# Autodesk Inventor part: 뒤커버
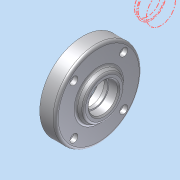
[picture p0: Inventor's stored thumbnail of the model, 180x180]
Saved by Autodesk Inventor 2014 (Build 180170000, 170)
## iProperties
Company: 한국ATC센터
Created: 2014-02
Part Number: 뒤커버
Document SubType Name: Modeling
Designer: KYOUNG IL JANG
Density: 2.71 g/cm^3
Mass: 97.9591 g
Surface Area: 115.525 cm^2
Volume: 36.1473 cm^3
Material: 알루미늄-6061
Vendor: CBT Solutions
Appearance: 알루미늄 - 평지
Author: KYOUNG IL JANG
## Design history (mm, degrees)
sketch "스케치1"
  geometry: L1 (-10.5, 0)-(10.5, 0); L2 (10.5, 0)-(10.5, 22.5); L3 (10.5, 22.5)-(5.5, 22.5); L4 (5.5, 22.5)-(5.5, 32.5); L5 (5.5, 32.5)-(-6.5, 32.5); L6 (-6.5, 32.5)-(-6.5, 17.5); L7 (-6.5, 17.5)-(-10.5, 15.191); L8 (-10.5, 15.191)-(-10.5, 0); 2 further points
  constraints: 16 end point, 3 parallel, 3 perpendicular, 1 coincident, 1 horizontal, 1 midpoint
  dimensions: "d0" = 21 distance of L1.start L1.end; "d1" = 65 diameter of L5 L1; "d2" = 45 diameter of L3 L1; "d3" = 35 diameter of L6.end L1; "d4" = 120 deg angle of L7 L6; "d5" = 12 distance of L4.end L5.end; "d6" = 5 distance of L2.end L3.end
revolve "회전1" sketch "스케치1" stored, may be unused: angle "d7" = 90 deg
sketch "스케치2"
  geometry: L1 (0, 0)-(32.5, 0); L2 (0, 0)-(18.738, 18.738); 1 further point
  constraints: 4 end point, 1 horizontal, 1 horizontal alignment, 1 other
  dimensions: "d8" = 45 deg angle of L1 L2; "d9" = 26.5 distance of L1.start L2.end
hole "구멍1" sketch "스케치2" at (18.738, 18.738) diameter "d10" = 3.4; stored, may be unused: countersink angle "d14" = 90 deg, drill point angle "d16" = 118 deg; dims "d11" = 6, "d12" = 6, "d13" = 3.3, "d15" = 8
fillet "모깎기1" dims "d20" = 2
hole "구멍2" diameter "d23" = 15; stored, may be unused: countersink angle "d27" = 90 deg, drill point angle "d29" = 0 deg; dims "d21" = 10, "d22" = 10, "d24" = 6, "d25" = 35, "d26" = 11, "d28" = 14
chamfer "모따기1" distance "d39" = 1; stored, may be unused: second distance "d40" = 2, angle "d41" = 45 deg
fillet "모깎기2" dims "d42" = 0.3
hole "구멍4" diameter "d46" = 17; stored, may be unused: countersink angle "d50" = 90 deg, drill point angle "d52" = 118 deg; dims "d44" = 10, "d45" = 10, "d47" = 6, "d48" = 22, "d49" = 7.3, "d51" = 8
chamfer "모따기2" distance "d53" = 1; stored, may be unused: second distance "d54" = 2, angle "d55" = 45 deg
fillet "모깎기3" dims "d56" = 0.3
node "솔리드1"
pattern_circular "원형 패턴1" dims angle "d18" = 360 deg
